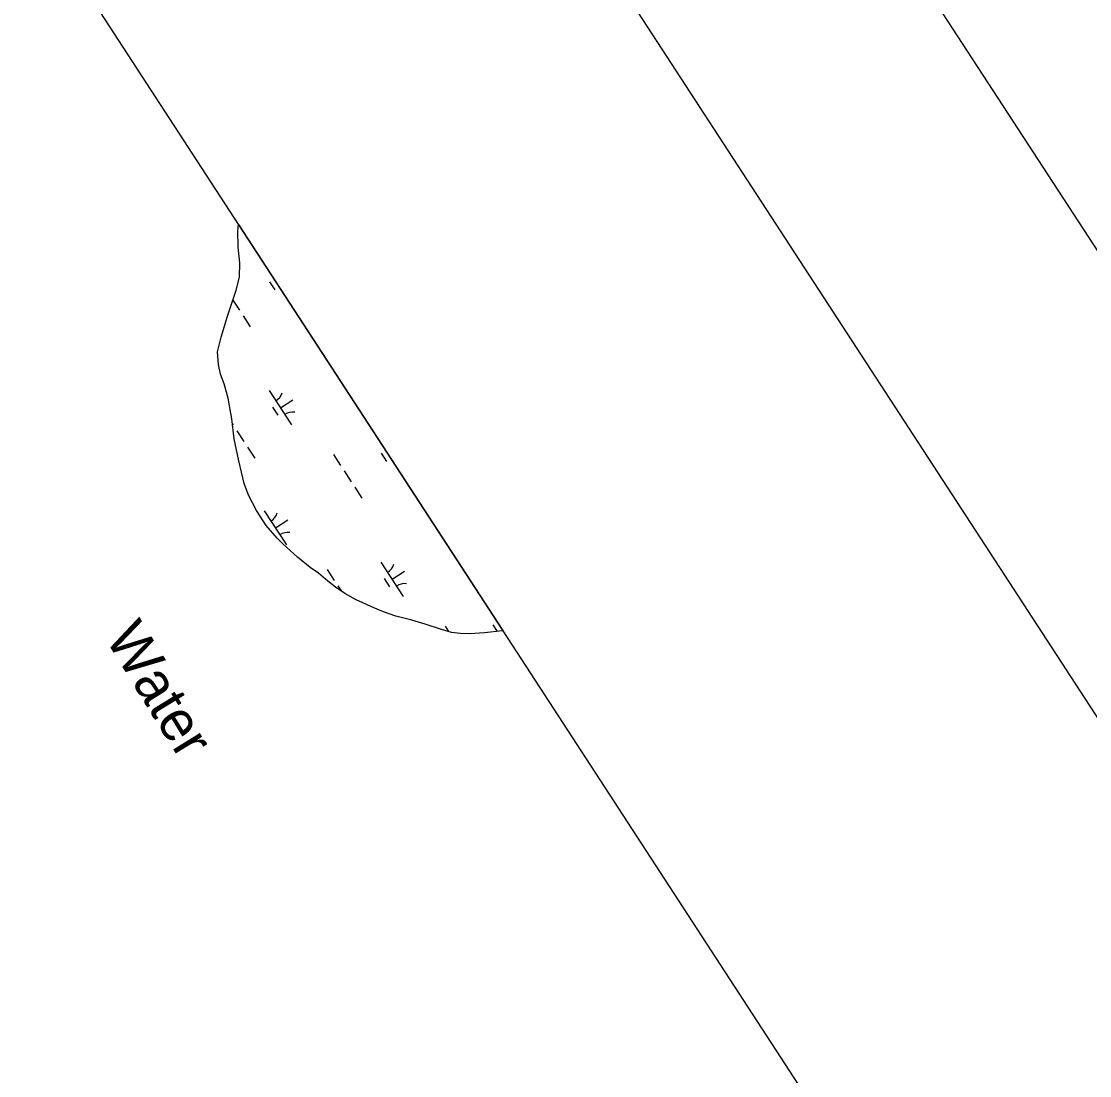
# Model space of a CAD drawing. Extents: x 3953924 to 3974542, y 193747 to 216192.
# Drawn here: x 3971678 to 3972988, y 201568 to 202861 of the extents above; entities that cross this region are included whole.
import ezdxf

# ---------------------------------------------------------------- set-up
doc = ezdxf.new("R2010")
doc.units = 0
for name, color, linetype in [('G-ANNO-NPLT', 7, 'Continuous'), ('V-ANNO-SYMB', 7, 'Continuous'), ('V-GRID-FRAM', 7, 'Continuous'), ('V-RIVR-IDEN', 7, 'Continuous'), ('V-WETL-SWMP', 7, 'Continuous')]:
    doc.layers.add(name, color=color, linetype=linetype)

msp = doc.modelspace()

# ---------------------------------------------------------------- linework, layer by layer
at = {"layer": 'G-ANNO-NPLT'}
msp.add_lwpolyline([(3954168.8, 209355.9), (3964170.5, 193991), (3974297.3, 200583), (3964295.6, 215947.9)], close=True, dxfattribs=at)
at = {"layer": 'V-ANNO-SYMB'}
msp.add_lwpolyline([(3955180.9, 208373.9), (3964205.1, 194510.7), (3973808.1, 200761.7), (3964783.9, 214624.9), (3955180.9, 208373.9)], dxfattribs=at)
at = {"layer": 'V-GRID-FRAM'}
msp.add_lwpolyline([(3964669.3, 213787.9), (3972946, 201072.9), (3966057, 196668.5), (3957950.8, 209463.9), (3964669.3, 213787.9)], dxfattribs=at)
at = {"layer": 'V-WETL-SWMP'}
for p, q in [((3971943.4, 202603.9), (3971944.2, 202611.9)), ((3971943.8, 202584.2), (3971943.4, 202603.9)), ((3971944.2, 202611.9), (3972268.4, 202113.9)), ((3971946, 202564.7), (3971943.8, 202584.2)), ((3971945.8, 202547.4), (3971946, 202564.7)), ((3971941.4, 202531.3), (3971945.8, 202547.4)), ((3971982.4, 202541.7), (3971989, 202531.7)), ((3971930.8, 202499.5), (3971941.4, 202531.3)), ((3971937.4, 202519.2), (3971945.6, 202506.7)), ((3971923.1, 202473.7), (3971930.8, 202499.5)), ((3971950, 202500), (3971958.7, 202486.5)), ((3971918.7, 202455.8), (3971923.1, 202473.7)), ((3971919.7, 202440.4), (3971918.7, 202455.8)), ((3971922.3, 202428.5), (3971919.7, 202440.4)), ((3971926.7, 202416.7), (3971922.3, 202428.5)), ((3971931.9, 202399), (3971926.7, 202416.7)), ((3971982, 202408.2), (3972009.3, 202366.2)), ((3971936, 202373.5), (3971931.9, 202399)), ((3971995.7, 202387.2), (3972010.8, 202397)), ((3971985.9, 202388), (3971992.5, 202378)), ((3971938.9, 202349.2), (3971936, 202373.5)), ((3971936.7, 202367.7), (3971938, 202365.7)), ((3971942.4, 202359), (3971951.1, 202345.6)), ((3971944.9, 202322), (3971938.9, 202349.2)), ((3971955.5, 202338.9), (3971964.2, 202325.5)), ((3972060.7, 202329.9), (3972069.4, 202316.4)), ((3972119.3, 202331.4), (3972125.9, 202321.3)), ((3971951.5, 202294.2), (3971944.9, 202322)), ((3972073.8, 202309.7), (3972082.5, 202296.3)), ((3971956.5, 202280), (3971951.5, 202294.2)), ((3972086.9, 202289.6), (3972095.6, 202276.2)), ((3971966.5, 202261.2), (3971956.5, 202280)), ((3971978.2, 202243), (3971966.5, 202261.2)), ((3971976, 202260.8), (3972003.3, 202218.9)), ((3971989.7, 202239.8), (3972004.8, 202249.7)), ((3971991.6, 202227.2), (3971978.2, 202243)), ((3971998.9, 202220.3), (3971991.6, 202227.2)), ((3972016.5, 202204), (3971998.9, 202220.3)), ((3972032.3, 202191.3), (3972016.5, 202204)), ((3972118.9, 202197.8), (3972146.2, 202155.9)), ((3972042.5, 202184.4), (3972032.3, 202191.3)), ((3972054, 202174.5), (3972042.5, 202184.4)), ((3972053.1, 202188.9), (3972061.8, 202175.5)), ((3972132.6, 202176.9), (3972147.7, 202186.7)), ((3972063.1, 202167), (3972054, 202174.5)), ((3972066.2, 202168.8), (3972070.5, 202162.1)), ((3972122.8, 202177.7), (3972129.4, 202167.6)), ((3972074.6, 202159.5), (3972063.1, 202167)), ((3972088.5, 202151.5), (3972074.6, 202159.5)), ((3972109.5, 202142.4), (3972088.5, 202151.5)), ((3972122.1, 202136.8), (3972109.5, 202142.4)), ((3972137.1, 202131.7), (3972122.1, 202136.8)), ((3972156.8, 202126.8), (3972137.1, 202131.7)), ((3972173, 202121.8), (3972156.8, 202126.8)), ((3972193.4, 202115.1), (3972173, 202121.8)), ((3972197.6, 202119.5), (3972202, 202112.7)), ((3972256.3, 202121.1), (3972261.5, 202113)), ((3972205.3, 202111.8), (3972193.4, 202115.1)), ((3972216.7, 202110.3), (3972205.3, 202111.8)), ((3972228, 202110), (3972216.7, 202110.3)), ((3972245.8, 202111), (3972228, 202110)), ((3972267.7, 202113.8), (3972245.8, 202111)), ((3972268.4, 202113.9), (3972267.7, 202113.8))]:
    msp.add_line(p, q, dxfattribs=at)
for centre, start, end in [((3971980.8, 202410.5), 302.2901, 343.8338), ((3972010.9, 202364.2), 82.2901, 123.8337), ((3971974.8, 202263.1), 302.2901, 343.8338), ((3972005, 202216.8), 82.2901, 123.8337), ((3972117.7, 202200.2), 302.2901, 343.8338), ((3972147.8, 202153.9), 82.2901, 123.8337)]:
    msp.add_arc(centre, 17.6, start, end, dxfattribs=at)

# ---------------------------------------------------------------- texts
at = {"layer": 'V-RIVR-IDEN'}
msp.add_text('Water', height=50, rotation=301.6613, dxfattribs=at).set_placement((3971780, 202105))

doc.saveas('drawing.dxf')
